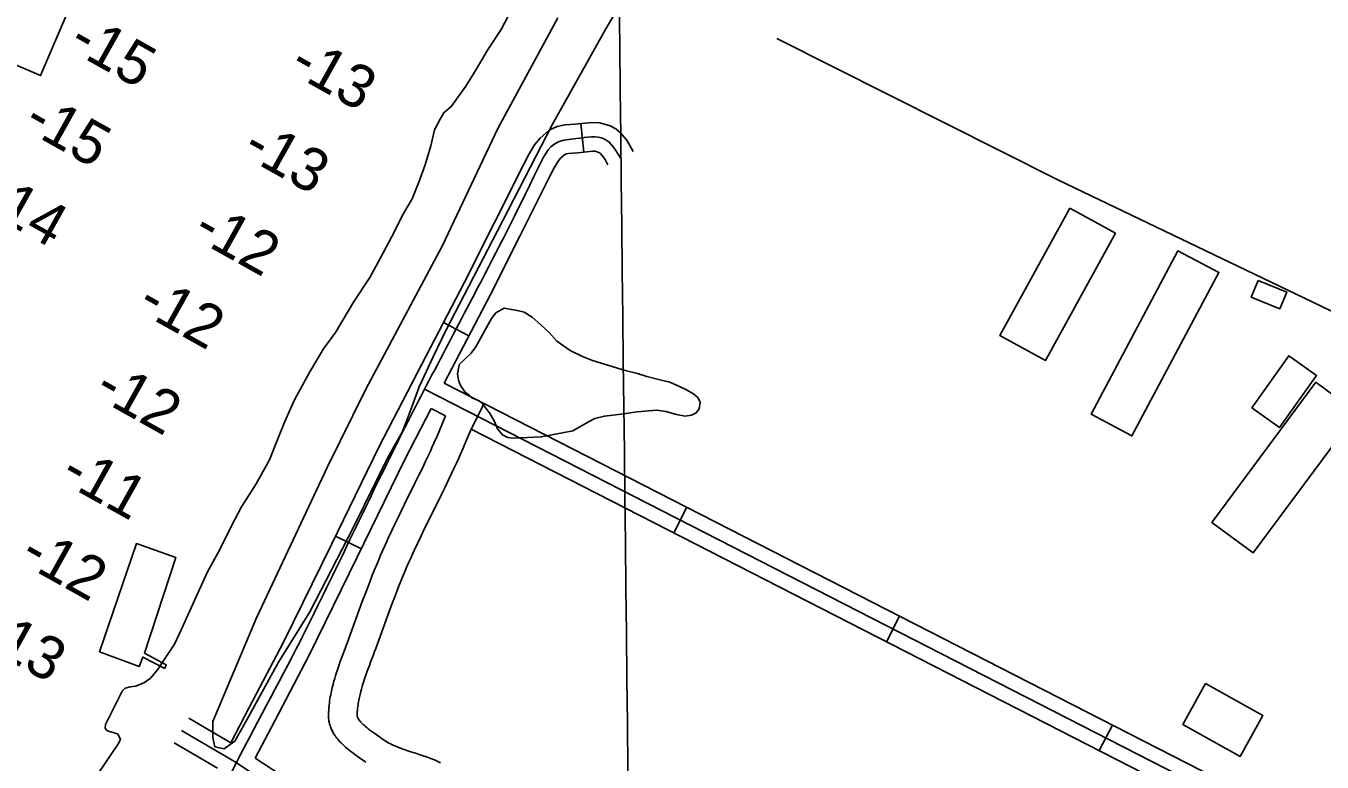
# Model space of a CAD drawing. Extents: x 3683402 to 3721514, y 487807 to 513565.
# Drawn here: x 3697569 to 3698925, y 495008 to 495778 of the extents above; entities that cross this region are included whole.
import ezdxf

# ---------------------------------------------------------------- set-up
doc = ezdxf.new("R2010")
doc.units = 0
for name, color, linetype in [('V-BLDG-OTLN', 7, 'Continuous'), ('V-CHAN-DOCK', 7, 'Continuous'), ('V-GRID-MAJR', 7, 'Continuous'), ('V-LEVE-TOET', 7, 'Continuous'), ('V-ROAD-CNTR', 7, 'Continuous'), ('V-TOPO-SHOR', 7, 'Continuous'), ('V-TOPO-SPOT', 7, 'Continuous')]:
    doc.layers.add(name, color=color, linetype=linetype)

msp = doc.modelspace()

# ---------------------------------------------------------------- linework, layer by layer
at = {"layer": 'V-BLDG-OTLN'}
for points in [[(3698661.044, 495587.569), (3698708.67, 495561.393), (3698635.454, 495428.185), (3698587.832, 495454.36100000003)], [(3698774.1920000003, 495543.166), (3698816.946, 495520.417), (3698725.984, 495349.466), (3698683.23, 495372.215)], [(3698857.9420000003, 495512.083), (3698887.892, 495499.873), (3698880.808, 495482.494), (3698850.856, 495494.704)], [(3698851.286, 495378.875), (3698890.112, 495433.268), (3698919.1920000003, 495412.512), (3698880.366, 495358.119)], [(3698809.687, 495258.99), (3698918.395, 495405.518), (3698961.522, 495373.52400000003), (3698852.812, 495226.994)], [(3698803.034, 495090.261), (3698862.933, 495056.956), (3698839.1520000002, 495014.18200000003), (3698779.252, 495047.484)]]:
    msp.add_lwpolyline(points, close=True, dxfattribs=at)
at = {"layer": 'V-CHAN-DOCK'}
for points in [[(3697563.451, 495881.909), (3697593.071, 495869.777), (3697598.343, 495882.618), (3697643.306, 495864.155), (3697584.431, 495726.314), (3697540.552, 495744.898), (3697591.293, 495864.905), (3697561.681, 495876.666), (3697563.451, 495881.909)], [(3697714.472, 495106.237), (3697691.185, 495118.11), (3697687.633, 495108.369), (3697646.049, 495123.641), (3697684.629, 495236.73600000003), (3697725.829, 495222.201), (3697692.972, 495122.23600000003), (3697715.896, 495109.983), (3697714.472, 495106.237)]]:
    msp.add_lwpolyline(points, dxfattribs=at)
at = {"layer": 'V-GRID-MAJR'}
msp.add_spline([(3698217.897, 493344.793), (3698148.292, 499402.231), (3698078.651, 505462.753), (3698009.0100000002, 511523.288), (3698008.975, 511526.359)], degree=3, dxfattribs=at)
at = {"layer": 'V-LEVE-TOET'}
msp.add_lwpolyline([(3698216.722, 495845.313), (3698175.754, 495775.362), (3698119.677, 495674.799), (3698061.895, 495563.3), (3698007.7830000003, 495458.979), (3697994.9790000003, 495432.199), (3697980.36, 495400.648), (3697969.96, 495372.012), (3697962.7, 495353.392), (3697947.983, 495327.53), (3697910.898, 495252.43200000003), (3697865.967, 495165.341), (3697833.23, 495112.607), (3697800.1520000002, 495052.27900000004), (3697787.738, 495030.246), (3697776.502, 495021.989), (3697766.508, 495024.18200000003), (3697764.435, 495034.105), (3697764.6180000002, 495050.704), (3697810.122, 495159.141), (3697884.166, 495316.446), (3697924.452, 495398.239), (3698004.318, 495548.061), (3698062.843, 495670.95300000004), (3698125.291, 495786.802)], dxfattribs=at)
at = {"layer": 'V-ROAD-CNTR'}
for p, q in [((3698152.7826555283, 495646.3016812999), (3698149.520662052, 495676.123621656)), ((3698032.4878961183, 495454.25906538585), (3698005.868949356, 495468.095037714)), ((3698048.3408644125, 495383.24420741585), (3698034.6728917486, 495356.538260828)), ((3698260.464440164, 495274.779424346), (3698246.797467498, 495248.0734777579)), ((3697919.924121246, 495231.4745109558), (3697892.9661751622, 495244.638484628)), ((3698483.012995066, 495160.88565213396), (3698469.3460224, 495134.1797055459)), ((3698705.562549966, 495046.99287992), (3698691.8955773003, 495020.286933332))]:
    msp.add_line(p, q, dxfattribs=at)
for points in [[(3698204.2225526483, 495646.98167994), (3698200.86655936, 495653.36166717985), (3698197.3745663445, 495659.00165590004), (3698190.93657922, 495666.582640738), (3698185.973589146, 495670.545632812), (3698180.0636009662, 495673.900626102), (3698169.48662212, 495676.9496200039), (3698161.063638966, 495677.3856191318), (3698143.71167367, 495675.488622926), (3698132.7466956, 495674.8136242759), (3698124.825711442, 495673.22462745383), (3698116.438728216, 495669.2076354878), (3698106.8457474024, 495661.039651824), (3698101.1947587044, 495654.0626657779), (3698095.385770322, 495644.428685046), (3698090.712779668, 495635.2337034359), (3698059.3548423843, 495572.6998285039), (3698027.8669053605, 495510.41595307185), (3697983.232994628, 495424.54712481), (3697938.716083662, 495338.3312972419), (3697888.610183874, 495235.7185024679), (3697838.439284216, 495133.53670683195), (3697802.729355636, 495065.1508436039), (3697783.4103942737, 495028.3329172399)], [(3698177.670605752, 495633.0177078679), (3698174.8066114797, 495638.46369697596), (3698173.0526149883, 495641.2956913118), (3698169.9486211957, 495644.95068400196), (3698169.1036228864, 495645.625682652), (3698168.3416244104, 495646.0586817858), (3698164.490632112, 495647.1676795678), (3698161.9236372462, 495647.30167929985), (3698146.265668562, 495645.5886827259), (3698136.634687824, 495644.99568391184), (3698134.4016922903, 495644.54868480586), (3698132.918695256, 495643.8376862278), (3698128.409704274, 495639.997693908), (3698125.812709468, 495636.79270031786), (3698121.6377178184, 495629.86871416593), (3698117.492726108, 495621.7137304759), (3698086.1507887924, 495559.2078554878), (3698054.5628519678, 495496.72998044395), (3698006.700947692, 495404.6471646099)], [(3697986.5719879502, 495398.0981777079), (3698892.7061756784, 494934.36810517)], [(3698006.700947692, 495404.6471646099), (3698887.814185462, 494953.7220664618)], [(3697992.9529751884, 495377.98221793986), (3697965.526030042, 495324.86532417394), (3697915.554129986, 495222.526528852), (3697865.2052306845, 495119.9807339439), (3697829.3093024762, 495051.238871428), (3697808.9133432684, 495012.3679491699)], [(3697892.4441762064, 495035.7999023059), (3697891.819177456, 495036.73490043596), (3697891.148178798, 495037.803898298), (3697890.5441800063, 495038.824896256), (3697889.948181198, 495039.89789410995), (3697889.0291830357, 495041.71689047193), (3697888.254184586, 495043.4688869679), (3697887.64218581, 495045.05088380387), (3697887.1591867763, 495046.4768809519), (3697886.7791875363, 495047.7638783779), (3697886.458188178, 495049.0138758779), (3697886.0621889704, 495050.91387207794), (3697885.820189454, 495052.496868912), (3697885.676189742, 495053.788866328), (3697885.55718998, 495055.53686283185), (3697885.5331900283, 495057.2708593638), (3697885.60718988, 495060.0768537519), (3697885.745189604, 495062.69084852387), (3697885.9351892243, 495065.21384347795), (3697886.174188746, 495067.6528385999), (3697886.45218819, 495070.0028339), (3697886.764187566, 495072.27082936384), (3697887.1031868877, 495074.4588249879), (3697887.465186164, 495076.5708207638), (3697887.8451854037, 495078.6098166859), (3697888.239184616, 495080.5778127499), (3697888.6541837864, 495082.5158088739), (3697889.489182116, 495086.1278016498), (3697890.3511803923, 495089.536794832), (3697891.211178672, 495092.709788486), (3697892.0591769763, 495095.6677825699), (3697892.88717532, 495098.42177706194), (3697893.6981736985, 495101.0207718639), (3697895.2471706, 495105.7607623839), (3697896.663167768, 495109.89975410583), (3697897.9361652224, 495113.50274689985), (3697900.178160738, 495119.6667345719), (3697901.8811573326, 495124.2467254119), (3697904.4071522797, 495130.97771194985), (3697905.644149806, 495134.2817053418), (3697906.8521473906, 495137.5376988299), (3697920.9351192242, 495176.0646217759), (3697924.5451120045, 495185.7536023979), (3697927.3041064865, 495193.01958786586), (3697929.409102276, 495198.471576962), (3697931.01709906, 495202.57456875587), (3697933.4580941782, 495208.69455651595), (3697935.956089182, 495214.8175442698), (3697938.053084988, 495219.83053424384), (3697940.124080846, 495224.664524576), (3697942.161076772, 495229.32251525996), (3697944.161072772, 495233.8135062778), (3697946.123068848, 495238.14749760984), (3697948.050064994, 495242.343489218), (3697951.809057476, 495250.3804731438), (3697955.390050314, 495257.88845812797), (3697958.783043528, 495264.900444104), (3697965.17703074, 495277.9284180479), (3697976.381008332, 495300.5953727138), (3697980.524000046, 495309.055355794), (3697984.104992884, 495316.456340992), (3697987.194986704, 495322.93032804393), (3697989.857981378, 495328.59931670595), (3697992.154976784, 495333.5643067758), (3697994.1349728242, 495337.910298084), (3697995.834969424, 495341.70129050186), (3697998.777963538, 495348.3992771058), (3698000.922959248, 495353.4152670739), (3698007.985945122, 495370.289233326)], [(3697992.9529751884, 495377.98221793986), (3698007.985945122, 495370.289233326)], [(3697917.3801263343, 495052.47986894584), (3697916.9951271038, 495053.05486779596), (3697916.768127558, 495053.41586707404), (3697916.574127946, 495053.744866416), (3697916.4601281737, 495053.9498660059), (3697916.1551287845, 495054.55486479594), (3697915.9781291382, 495054.954863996), (3697915.85212939, 495055.28086334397), (3697915.763129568, 495055.5428628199), (3697915.7031296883, 495055.7458624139), (3697915.6861297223, 495055.8118622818), (3697915.596129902, 495056.24186142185), (3697915.568129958, 495056.428861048), (3697915.56212997, 495056.4768609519), (3697915.543130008, 495056.75886038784), (3697915.539130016, 495057.0788597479), (3697915.5871299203, 495058.8948561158), (3697915.685129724, 495060.77485235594), (3697915.8251294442, 495062.61984866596), (3697916.0021290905, 495064.42484505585), (3697916.21212867, 495066.196841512), (3697916.450128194, 495067.9328380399), (3697916.7131276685, 495069.63083464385), (3697916.9971271, 495071.2908313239), (3697917.2991264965, 495072.9118280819), (3697917.6171258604, 495074.4938249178), (3697917.9381252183, 495075.99982190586), (3697918.6491237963, 495079.0698157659), (3697919.373122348, 495081.934810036), (3697920.1091208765, 495084.649804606), (3697920.845119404, 495087.21379947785), (3697921.573117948, 495089.63779462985), (3697922.276116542, 495091.8927901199), (3697923.6991136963, 495096.24478141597), (3697925.001111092, 495100.0497738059), (3697926.1761087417, 495103.380767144), (3697928.3341044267, 495109.3087552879), (3697929.985101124, 495113.748746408), (3697932.499096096, 495120.4477330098), (3697933.756093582, 495123.8057262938), (3697935.0040910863, 495127.1717195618), (3697949.079062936, 495165.6766425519), (3697952.6250558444, 495175.1916235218), (3697955.3200504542, 495182.29360931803), (3697957.36704636, 495187.59359871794), (3697958.9150432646, 495191.5425908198), (3697961.280038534, 495197.470578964), (3697963.684033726, 495203.3615671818), (3697965.681029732, 495208.13655763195), (3697967.656025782, 495212.7485484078), (3697969.6070218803, 495217.21053948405), (3697971.529018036, 495221.525530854), (3697973.419014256, 495225.70152250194), (3697975.268010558, 495229.72751444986), (3697978.9350032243, 495237.56849876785), (3697982.429996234, 495244.896484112), (3697985.750989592, 495251.756470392), (3697992.0889769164, 495264.6724445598), (3698003.2989544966, 495287.3513992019), (3698007.4979460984, 495295.9253820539), (3698011.144938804, 495303.46236697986), (3698014.308932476, 495310.09235372), (3698017.047926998, 495315.92334205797), (3698019.418922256, 495321.04633181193), (3698021.470918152, 495325.5523227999), (3698023.254914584, 495329.52731484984), (3698026.3039084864, 495336.4673009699), (3698028.552903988, 495341.7272904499), (3698034.76689156, 495356.5832607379)], [(3698034.76689156, 495356.5832607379), (3698870.667219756, 494928.79611631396)], [(3697783.4103942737, 495028.3329172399), (3697739.508482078, 495054.28386533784)], [(3698002.780955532, 495007.59795871), (3698000.608959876, 495008.62595665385), (3697998.5049640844, 495009.5659547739), (3697996.470968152, 495010.43195304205), (3697994.500972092, 495011.231951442), (3697992.56697596, 495011.9869499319), (3697988.9569831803, 495013.3219472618), (3697985.5529899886, 495014.5109448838), (3697982.3759963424, 495015.57594275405), (3697976.591007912, 495017.44793900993), (3697971.619017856, 495019.0459358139), (3697967.3890263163, 495020.4429330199), (3697963.789033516, 495021.689930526), (3697960.7260396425, 495022.8149282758), (3697958.118044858, 495023.83292624), (3697955.89204931, 495024.756924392), (3697953.988053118, 495025.5949227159), (3697952.3570563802, 495026.351921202), (3697950.9600591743, 495027.03391983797), (3697949.759061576, 495027.646918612), (3697948.7680635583, 495028.173917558), (3697946.92206725, 495029.2079154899), (3697945.6260698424, 495029.9789139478), (3697944.714071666, 495030.54891280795), (3697943.2670745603, 495031.4979109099), (3697941.770077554, 495032.54190882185), (3697940.474080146, 495033.46790697), (3697937.7860855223, 495035.36690317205), (3697935.2680905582, 495037.13789962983), (3697932.950095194, 495038.77989634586), (3697930.8350994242, 495040.30489329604), (3697928.9171032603, 495041.7238904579), (3697927.188106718, 495043.04288782), (3697925.64210981, 495044.26688537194), (3697924.2661125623, 495045.399883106), (3697923.050114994, 495046.44788100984), (3697921.9821171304, 495047.4128790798), (3697921.0471190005, 495048.30187730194), (3697920.2351206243, 495049.11287568), (3697919.531122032, 495049.8558741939), (3697918.924123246, 495050.533872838), (3697918.4081242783, 495051.14287161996), (3697917.964125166, 495051.6978705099), (3697917.583125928, 495052.2028694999), (3697917.1421268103, 495052.8248682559)], [(3698612.941735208, 494527.71991846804), (3697873.4512141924, 494952.1430696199), (3697787.1253868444, 495008.7119564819), (3697731.875497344, 495041.37189116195)], [(3697924.4641121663, 495008.03595783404), (3697923.0961149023, 495009.01395587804), (3697920.50212009, 495010.84695221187), (3697917.9661251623, 495012.62994864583), (3697915.506130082, 495014.37394515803), (3697913.143134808, 495016.076941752), (3697910.8971393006, 495017.73793842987), (3697908.7801435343, 495019.3529352), (3697906.7901475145, 495020.9269320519), (3697904.93215123, 495022.45992898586), (3697903.2001546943, 495023.95192600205), (3697901.5941579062, 495025.4029231), (3697900.10716088, 495026.81392027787), (3697898.7331636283, 495028.1889175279), (3697897.469166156, 495029.5239148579), (3697896.3061684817, 495030.81991226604), (3697895.236170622, 495032.08290974), (3697894.2621725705, 495033.30390729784), (3697893.373174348, 495034.4829049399), (3697892.68217573, 495035.45490299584)], [(3697769.41742226, 495001.7549703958), (3697724.2425126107, 495028.45891698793)], [(3698066.902827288, 494858.409257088), (3697881.30219849, 494964.93204404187), (3697808.9133432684, 495012.3679491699)]]:
    msp.add_lwpolyline(points, dxfattribs=at)
msp.add_spline([(3698190.9465791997, 495639.99969390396), (3698174.2026126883, 495659.979653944), (3698144.988671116, 495660.53865282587), (3698124.6787117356, 495656.52266085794), (3698104.1027528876, 495628.4737169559), (3698041.214878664, 495503.57296675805), (3697952.1210568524, 495331.59831070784), (3697851.8222574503, 495126.75872038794), (3697780.0814009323, 494989.70299449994), (3697710.7195396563, 494854.7412644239), (3697658.8186434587, 494764.35844518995), (3697641.0526789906, 494692.2135894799), (3697671.80261749, 494617.64473861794), (3697762.559435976, 494578.2288174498), (3697846.8652673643, 494530.8729121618), (3697903.70715368, 494493.01098788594)], degree=3, dxfattribs=at)
at = {"layer": 'V-TOPO-SHOR'}
for points in [[(3698076.5810000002, 495794.601), (3698066.079, 495774.647), (3698051.731, 495753.07800000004), (3698040.074, 495732.716), (3698029.137, 495715.468), (3698014.396, 495694.278), (3698006.3740000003, 495687.548), (3698002.227, 495680.886), (3697996.613, 495669.54600000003), (3697992.644, 495652.81), (3697986.793, 495632.938), (3697980.133, 495614.99100000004), (3697973.077, 495597.424), (3697964.044, 495582.148), (3697951.299, 495557.506), (3697940.058, 495535.601), (3697928.787, 495515.246), (3697911.801, 495489.365), (3697892.98, 495457.637), (3697880.4930000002, 495440.362), (3697866.186, 495416.466), (3697850.036, 495387.112), (3697839.97, 495364.45300000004), (3697832.5330000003, 495346.492), (3697824.012, 495324.249), (3697809.725, 495299.19), (3697794.6410000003, 495275.27900000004), (3697784.139, 495255.32800000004), (3697771.409, 495229.91000000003), (3697759.018, 495207.21), (3697748.572, 495184.156), (3697731.776, 495147.425), (3697724.307, 495131.401), (3697714.872, 495116.893), (3697706.559, 495104.732), (3697699.348, 495096.077), (3697693.228, 495091.32), (3697683.992, 495087.666), (3697678.1920000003, 495086.79000000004), (3697672.787, 495085.532), (3697669.742, 495082.376), (3697652.139, 495047.57), (3697651.8200000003, 495043.689), (3697653.798, 495041.398), (3697656.5300000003, 495040.284), (3697662.764, 495038.455), (3697665.109, 495037.332), (3697667.911, 495032.343), (3697666.056, 495027.66000000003), (3697606.7430000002, 494940.179)], [(3698354.704, 495765.32300000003), (3698648.5, 495617.244), (3698914.688, 495489.68), (3699116.775, 495392.206), (3699122.4790000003, 495390.604), (3699127.555, 495392.396), (3699133.708, 495397.612), (3699251.224, 495557.481)], [(3698032.936, 495391.569), (3698028.257, 495395.712), (3698023.534, 495402.155), (3698021.515, 495407.879), (3698020.632, 495414.392), (3698022.039, 495421.713), (3698022.758, 495424.41500000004), (3698034.841, 495436.148), (3698039.715, 495442.761), (3698047.164, 495455.94800000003), (3698049.015, 495459.82), (3698056.091, 495472.233), (3698060.597, 495478.072), (3698069.34, 495483.219), (3698073.1920000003, 495482.518), (3698082.822, 495480.76900000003), (3698090.149, 495478.977), (3698098.6890000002, 495473.751), (3698107.668, 495465.463), (3698116.255, 495457.549), (3698124.48, 495448.479), (3698138.4760000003, 495438.74), (3698151.258, 495432.439), (3698161.696, 495428.398), (3698196.06, 495417.867), (3698208.788, 495414.635), (3698218.438, 495411.733), (3698233.485, 495407.775), (3698242.74, 495405.635), (3698252.801, 495401.20300000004), (3698259.3880000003, 495397.862), (3698267.531, 495393.4), (3698272.2120000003, 495389.257), (3698274.219, 495384.3), (3698273.181, 495377.753), (3698270.187, 495373.479), (3698265.237, 495371.087), (3698258.722, 495370.204), (3698249.475, 495371.961), (3698238.289, 495374.837), (3698229.049, 495376.20900000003), (3698208.339, 495374.691), (3698191.873, 495372.099), (3698174.242, 495370.251), (3698164.301, 495367.771), (3698157.453, 495364.195), (3698141.108, 495354.691), (3698130.392, 495352.581), (3698108.194, 495348.352), (3698093.615, 495347.711), (3698078.65, 495347.06200000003), (3698073.261, 495347.735), (3698067.449, 495350.705), (3698062.352, 495356.759), (3698059.145, 495364.384), (3698053.992, 495373.50800000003), (3698046.1380000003, 495383.354), (3698043.021, 495385.98600000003), (3698035.664, 495389.314), (3698032.936, 495391.569)]]:
    msp.add_lwpolyline(points, dxfattribs=at)

# ---------------------------------------------------------------- texts
at = {"layer": 'V-TOPO-SPOT'}
for s, p in [('-15', (3697611.7462386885, 495754.3562290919)), ('-13', (3697842.6594457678, 495730.6139793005)), ('-15', (3697564.6262386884, 495671.2362290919)), ('-13', (3697793.579445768, 495643.4639793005)), ('-14', (3697519.3862386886, 495587.89622909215)), ('-12', (3697741.6562386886, 495557.5562290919)), ('-12', (3697683.6762386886, 495481.0362290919)), ('-12', (3697638.6262386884, 495391.37622909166)), ('-11', (3697603.0311781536, 495302.63533084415)), ('-12', (3697560.8462386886, 495217.7862290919)), ('-13', (3697518.129445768, 495132.7539793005))]:
    msp.add_text(s, height=45, rotation=330.79328332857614, dxfattribs=at).set_placement(p)

doc.saveas('drawing.dxf')
